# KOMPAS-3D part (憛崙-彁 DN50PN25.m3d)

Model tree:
1. Объединить компоненты:1  (labels: СЕНС-ПР DN50PN25)

Referenced files in D:\Савин\!СЕНСОР\3D для заказчика\!Новый перечень\СЕНС-ПР\1. СЕНС-ПР\DN50\: СЕНС-ПР DN50PN25.a3d
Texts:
  СЕНС-ПР DN50PN25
